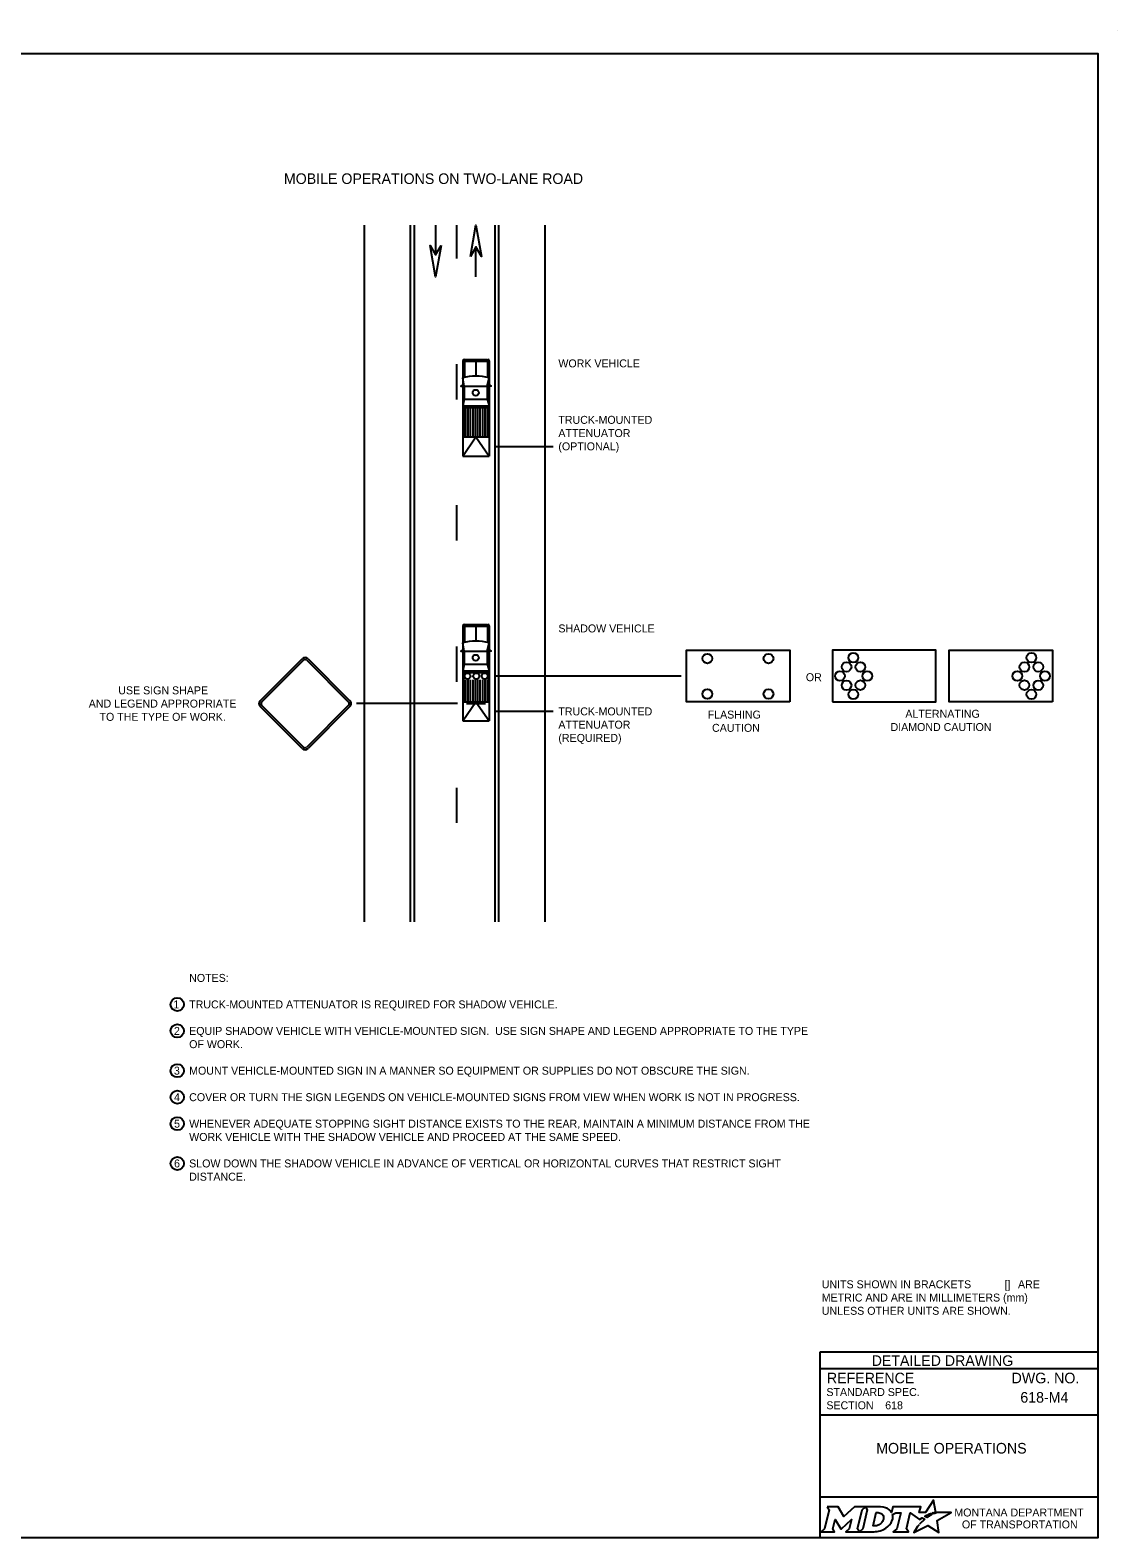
# Model space of a CAD drawing. Extents: x 49991.4 to 50021, y 49987.6 to 50011.4.
# Drawn here: x 50008.69 to 50016.9, y 49987.8 to 49999.18 of the extents above; entities that cross this region are included whole.
import ezdxf

# ---------------------------------------------------------------- set-up
doc = ezdxf.new("R2010")
doc.units = 0
for name, color, linetype in [('Default', 7, 'Continuous'), ('Level 1', 7, 'Continuous'), ('Level 2', 7, 'Continuous'), ('Level 3', 7, 'Continuous'), ('Level 5', 7, 'Continuous')]:
    doc.layers.add(name, color=color, linetype=linetype)

msp = doc.modelspace()

# ---------------------------------------------------------------- linework, layer by layer
at = {"layer": 'Default'}
for points in [[(50015.513, 49987.981), (50015.502, 49987.987), (50015.514, 49987.99), (50015.526, 49987.991), (50015.508, 49988.082), (50015.449, 49987.99), (50015.401, 49987.99), (50015.412, 49988.034), (50015.202, 49988.034), (50015.192, 49987.991), (50015.186, 49988)], [(50014.706, 49988.034), (50014.72, 49988.01), (50014.686, 49987.867), (50014.66, 49987.845), (50014.762, 49987.845), (50014.749, 49987.867), (50014.765, 49987.937), (50014.809, 49987.868), (50014.814, 49987.868), (50014.889, 49987.938), (50014.872, 49987.867), (50014.848, 49987.845), (50014.949, 49987.845), (50014.936, 49987.868), (50014.969, 49988.011)], [(50014.969, 49988.011), (50014.994, 49988.034), (50014.912, 49988.034), (50014.832, 49987.961), (50014.788, 49988.034), (50014.706, 49988.034)], [(50015.108, 49988.034), (50014.994, 49988.034), (50015.009, 49988.011), (50014.975, 49987.867), (50014.949, 49987.845), (50015.06, 49987.845)], [(50015.132, 49987.947), (50015.13, 49987.939), (50015.127, 49987.93), (50015.123, 49987.922), (50015.118, 49987.914), (50015.111, 49987.907), (50015.103, 49987.901), (50015.095, 49987.896), (50015.086, 49987.892), (50015.077, 49987.89), (50015.067, 49987.889), (50015.052, 49987.889), (50015.075, 49987.989), (50015.091, 49987.989), (50015.099, 49987.988), (50015.106, 49987.986), (50015.113, 49987.983), (50015.119, 49987.979), (50015.124, 49987.974), (50015.128, 49987.968), (50015.13, 49987.962), (50015.132, 49987.955), (50015.132, 49987.952), (50015.132, 49987.947)], [(50015.199, 49987.975), (50015.224, 49987.988), (50015.261, 49987.988), (50015.232, 49987.867), (50015.205, 49987.845), (50015.321, 49987.845), (50015.304, 49987.867), (50015.332, 49987.988), (50015.403, 49987.936), (50015.424, 49987.951), (50015.444, 49987.94)], [(50015.388, 49987.884), (50015.373, 49987.86), (50015.368, 49987.852), (50015.362, 49987.844), (50015.36, 49987.839), (50015.465, 49987.893), (50015.549, 49987.838), (50015.536, 49987.93), (50015.643, 49987.989), (50015.594, 49987.989), (50015.564, 49987.99), (50015.543, 49987.99), (50015.536, 49987.989), (50015.531, 49987.987), (50015.523, 49987.985), (50015.513, 49987.981)], [(50015.462, 49987.954), (50015.46, 49987.952), (50015.442, 49987.961), (50015.452, 49987.967), (50015.456, 49987.969), (50015.465, 49987.973), (50015.47, 49987.976), (50015.478, 49987.979), (50015.485, 49987.982), (50015.497, 49987.974), (50015.493, 49987.972), (50015.489, 49987.97), (50015.484, 49987.967), (50015.479, 49987.965), (50015.478, 49987.963), (50015.475, 49987.962), (50015.472, 49987.96), (50015.47, 49987.959), (50015.467, 49987.957), (50015.465, 49987.955), (50015.462, 49987.954)], [(50015.106, 49987.852), (50015.114, 49987.855), (50015.127, 49987.86), (50015.148, 49987.871)], [(50015.402, 49987.9), (50015.402, 49987.9)]]:
    msp.add_lwpolyline(points, dxfattribs=at)
for centre, radius, start, end in [((50015.087, 49987.973), 0.118, 300.9103, 339.1383), ((50015.131, 49987.955), 0.0709, 339.5329, 15.8582)]:
    msp.add_arc(centre, radius, start, end, dxfattribs=at)
for centre, major_axis, ratio, start_param, end_param in [((50015.106, 49987.986), (0.0834, -0.0037), 0.568097, 0.61298, 1.570796), ((50015.161, 49987.994), (0.0361, -0.0295), 0.469099, 1.225588, 1.570796), ((50015.433, 49987.93), (-0.0112, -0.0097), 0.021651, 3.157348, 6.283185), ((50015.06, 49987.993), (0, 0.148), 0.987302, 3.139398, 3.456847), ((50015.395, 49987.892), (-0.00694, -0.00806), 0.008222, 0, 3.137361), ((50015.412, 49987.911), (-0.0098, -0.0102), 0.016458, 3.141593, 6.279097)]:
    msp.add_ellipse(centre, major_axis=major_axis, ratio=ratio, start_param=start_param, end_param=end_param, dxfattribs=at)
at = {"layer": 'Level 1'}
for p, q in [((50016.9, 49999.176), (50016.9, 49999.176)), ((50011.213, 49992.446), (50011.213, 49997.704)), ((50011.561, 49992.446), (50011.561, 49997.704)), ((50011.59, 49992.446), (50011.59, 49997.704)), ((50011.75, 49997.704), (50011.75, 49997.479)), ((50011.75, 49997.704), (50011.75, 49997.479)), ((50011.91, 49997.453), (50011.91, 49997.704)), ((50012.199, 49992.446), (50012.199, 49997.704)), ((50012.228, 49992.446), (50012.228, 49997.704)), ((50012.577, 49992.446), (50012.577, 49997.704)), ((50012.055, 49997.314), (50012.055, 49997.54)), ((50012.055, 49997.314), (50012.055, 49997.54)), ((50011.968, 49996.678), (50011.96, 49996.688)), ((50011.968, 49996.691), (50012.143, 49996.691)), ((50012.143, 49996.678), (50012.151, 49996.687)), ((50011.91, 49996.389), (50011.91, 49996.656)), ((50011.955, 49996.678), (50011.955, 49995.962)), ((50011.968, 49996.678), (50012.143, 49996.678)), ((50011.968, 49996.678), (50011.968, 49996.56)), ((50012.055, 49996.678), (50012.055, 49996.573)), ((50012.143, 49996.678), (50012.143, 49996.56)), ((50012.154, 49996.68), (50012.154, 49995.962)), ((50011.966, 49996.49), (50011.955, 49996.551)), ((50011.966, 49996.49), (50012.14, 49996.49)), ((50011.966, 49996.49), (50011.966, 49996.391)), ((50012.14, 49996.49), (50012.154, 49996.551)), ((50012.14, 49996.49), (50012.14, 49996.391)), ((50011.966, 49996.39), (50011.955, 49996.34)), ((50011.966, 49996.39), (50012.14, 49996.39)), ((50012.14, 49996.39), (50012.154, 49996.34)), ((50011.955, 49996.34), (50012.154, 49996.34)), ((50011.955, 49996.329), (50012.154, 49996.329)), ((50011.961, 49996.329), (50011.961, 49996.214)), ((50011.976, 49996.329), (50011.976, 49996.107)), ((50011.994, 49996.329), (50011.994, 49996.107)), ((50012.012, 49996.329), (50012.012, 49996.107)), ((50012.031, 49996.329), (50012.031, 49996.107)), ((50012.049, 49996.329), (50012.049, 49996.107)), ((50012.067, 49996.329), (50012.067, 49996.107)), ((50012.085, 49996.329), (50012.085, 49996.107)), ((50012.104, 49996.329), (50012.104, 49996.107)), ((50012.122, 49996.329), (50012.122, 49996.107)), ((50012.14, 49996.329), (50012.14, 49996.107)), ((50012.148, 49996.329), (50012.148, 49996.214)), ((50011.962, 49996.214), (50011.955, 49996.214)), ((50011.962, 49996.161), (50011.955, 49996.161)), ((50011.961, 49996.161), (50011.961, 49996.107)), ((50011.966, 49996.209), (50011.966, 49996.165)), ((50012.143, 49996.209), (50012.143, 49996.165)), ((50012.148, 49996.214), (50012.154, 49996.214)), ((50012.148, 49996.161), (50012.154, 49996.161)), ((50012.148, 49996.161), (50012.148, 49996.107)), ((50011.955, 49996.107), (50012.154, 49996.107)), ((50011.955, 49995.962), (50012.154, 49995.962)), ((50011.91, 49995.324), (50011.91, 49995.59)), ((50011.955, 49994.679), (50011.955, 49993.963)), ((50011.968, 49994.678), (50011.96, 49994.688)), ((50011.968, 49994.691), (50012.143, 49994.691)), ((50011.968, 49994.678), (50012.143, 49994.678)), ((50011.968, 49994.678), (50011.968, 49994.561)), ((50012.055, 49994.678), (50012.055, 49994.574)), ((50012.143, 49994.678), (50012.151, 49994.687)), ((50012.143, 49994.678), (50012.143, 49994.561)), ((50012.154, 49994.681), (50012.154, 49993.963)), ((50011.91, 49994.258), (50011.91, 49994.525)), ((50011.966, 49994.49), (50011.955, 49994.552)), ((50012.14, 49994.49), (50012.154, 49994.552)), ((50010.427, 49994.116), (50010.742, 49994.432)), ((50010.437, 49994.105), (50010.753, 49994.421)), ((50010.777, 49994.421), (50011.093, 49994.105)), ((50010.788, 49994.432), (50011.103, 49994.116)), ((50011.966, 49994.49), (50012.14, 49994.49)), ((50011.966, 49994.49), (50011.966, 49994.391)), ((50012.14, 49994.49), (50012.14, 49994.391)), ((50011.966, 49994.391), (50011.955, 49994.341)), ((50011.955, 49994.341), (50012.154, 49994.341)), ((50011.955, 49994.329), (50012.154, 49994.329)), ((50011.961, 49994.329), (50011.961, 49994.214)), ((50011.966, 49994.391), (50012.14, 49994.391)), ((50012.14, 49994.391), (50012.154, 49994.341)), ((50012.148, 49994.329), (50012.148, 49994.214)), ((50011.962, 49994.214), (50011.955, 49994.214)), ((50011.966, 49994.209), (50011.966, 49994.166)), ((50011.976, 49994.274), (50011.976, 49994.107)), ((50011.994, 49994.274), (50011.994, 49994.107)), ((50012.012, 49994.274), (50012.012, 49994.107)), ((50012.031, 49994.274), (50012.031, 49994.107)), ((50012.049, 49994.274), (50012.049, 49994.107)), ((50012.067, 49994.274), (50012.067, 49994.107)), ((50012.085, 49994.274), (50012.085, 49994.107)), ((50012.104, 49994.274), (50012.104, 49994.107)), ((50012.122, 49994.274), (50012.122, 49994.107)), ((50012.14, 49994.274), (50012.14, 49994.107)), ((50012.143, 49994.209), (50012.143, 49994.166)), ((50012.148, 49994.214), (50012.154, 49994.214)), ((50010.742, 49993.755), (50010.427, 49994.071)), ((50010.753, 49993.766), (50010.437, 49994.082)), ((50010.753, 49993.766), (50010.437, 49994.082)), ((50010.437, 49994.082), (50010.753, 49993.766)), ((50011.093, 49994.082), (50010.777, 49993.766)), ((50011.103, 49994.071), (50010.788, 49993.755)), ((50011.962, 49994.161), (50011.955, 49994.161)), ((50011.955, 49994.107), (50012.154, 49994.107)), ((50011.961, 49994.161), (50011.961, 49994.107)), ((50011.983, 49994.094), (50012.126, 49994.094)), ((50012.148, 49994.161), (50012.154, 49994.161)), ((50012.148, 49994.161), (50012.148, 49994.107)), ((50011.955, 49993.963), (50012.154, 49993.963)), ((50011.91, 49993.193), (50011.91, 49993.459))]:
    msp.add_line(p, q, dxfattribs=at)
for points in [[(49999.384, 49998.999), (50016.75, 49998.999), (50016.75, 49987.799), (49999.384, 49987.799)], [(50012.013, 49997.468), (50012.055, 49997.704), (50012.097, 49997.468), (50012.055, 49997.54)], [(50011.792, 49997.551), (50011.75, 49997.314), (50011.708, 49997.551), (50011.75, 49997.479)], [(50014.424, 49994.107), (50013.644, 49994.107), (50013.644, 49994.497), (50014.424, 49994.497)], [(50014.424, 49994.107), (50013.644, 49994.107), (50013.644, 49994.497), (50014.424, 49994.497)]]:
    msp.add_lwpolyline(points, close=True, dxfattribs=at)
for points in [[(50011.963, 49996.489), (50011.95, 49996.497), (50011.94, 49996.489), (50011.963, 49996.489)], [(50012.147, 49996.489), (50012.16, 49996.497), (50012.17, 49996.489), (50012.147, 49996.489)], [(50011.955, 49995.962), (50012.055, 49996.107), (50012.154, 49995.962)], [(50011.963, 49994.489), (50011.95, 49994.497), (50011.94, 49994.489), (50011.963, 49994.489)], [(50012.147, 49994.49), (50012.16, 49994.497), (50012.17, 49994.49), (50012.147, 49994.49)], [(50014.745, 49994.107), (50015.525, 49994.107), (50015.525, 49994.497), (50014.745, 49994.497), (50014.745, 49994.107)], [(50016.407, 49994.107), (50015.627, 49994.107), (50015.627, 49994.497), (50016.407, 49994.497), (50016.407, 49994.107)], [(50011.955, 49993.963), (50012.055, 49994.107), (50012.154, 49993.963)]]:
    msp.add_lwpolyline(points, dxfattribs=at)
for centre, radius in [((50012.053, 49996.44), 0.0227), ((50012.053, 49994.44), 0.0227), ((50013.802, 49994.434), 0.0366), ((50014.263, 49994.434), 0.0366), ((50014.903, 49994.44), 0.0366), ((50016.248, 49994.44), 0.0366), ((50011.991, 49994.302), 0.0227), ((50012.057, 49994.302), 0.0227), ((50012.121, 49994.302), 0.0227), ((50014.802, 49994.302), 0.0366), ((50014.852, 49994.371), 0.0366), ((50014.957, 49994.37), 0.0366), ((50015.009, 49994.302), 0.0366), ((50016.142, 49994.302), 0.0366), ((50016.195, 49994.37), 0.0366), ((50016.299, 49994.371), 0.0366), ((50016.35, 49994.302), 0.0366), ((50013.802, 49994.167), 0.0366), ((50014.263, 49994.167), 0.0366), ((50014.852, 49994.232), 0.0366), ((50014.903, 49994.163), 0.0366), ((50014.957, 49994.233), 0.0366), ((50016.195, 49994.233), 0.0366), ((50016.248, 49994.163), 0.0366), ((50016.299, 49994.232), 0.0366)]:
    msp.add_circle(centre, radius, dxfattribs=at)
for centre, radius, start, end in [((50011.968, 49996.678), 0.0135, 92.7859, 176.3711), ((50012.143, 49996.679), 0.0118, 5.1286, 87.8426), ((50012.054, 49996.19), 0.375, 74.595, 105.405), ((50011.962, 49996.209), 0.00458, 0, 90), ((50011.962, 49996.165), 0.00458, 270, 0), ((50012.148, 49996.209), 0.00458, 90, 180), ((50012.148, 49996.165), 0.00458, 180, 270), ((50011.968, 49994.678), 0.0135, 92.7859, 176.3711), ((50012.143, 49994.68), 0.0118, 5.1286, 87.8426), ((50012.054, 49994.19), 0.375, 74.595, 105.405), ((50010.765, 49994.409), 0.0319, 45.0001, 134.9999), ((50010.765, 49994.409), 0.0168, 45.0001, 134.9999), ((50011.962, 49994.209), 0.00458, 0, 90), ((50012.148, 49994.209), 0.00458, 90, 180), ((50010.449, 49994.094), 0.0319, 134.9999, 225.0001), ((50010.449, 49994.094), 0.0168, 134.9999, 225.0001), ((50011.081, 49994.094), 0.0168, 314.9999, 45.0001), ((50011.081, 49994.094), 0.0319, 314.9999, 45.0001), ((50011.962, 49994.166), 0.00458, 270, 0), ((50012.148, 49994.166), 0.00458, 180, 270), ((50010.765, 49993.778), 0.0319, 225.0001, 314.9999), ((50010.765, 49993.778), 0.0168, 225.0001, 314.9999)]:
    msp.add_arc(centre, radius, start, end, dxfattribs=at)
at = {"layer": 'Level 2'}
for centre in [(50009.8, 49991.824), (50009.8, 49991.624), (50009.8, 49991.324), (50009.8, 49991.124), (50009.8, 49990.924), (50009.8, 49990.624)]:
    msp.add_circle(centre, 0.05, dxfattribs=at)
at = {"layer": 'Level 3'}
for p, q in [((50012.194, 49996.035), (50012.637, 49996.035)), ((50013.604, 49994.302), (50012.194, 49994.302)), ((50011.915, 49994.094), (50011.153, 49994.094)), ((50012.637, 49994.035), (50012.194, 49994.035))]:
    msp.add_line(p, q, dxfattribs=at)
at = {"layer": 'Level 5'}
for p, q in [((50016.75, 49989.199), (50014.65, 49989.199)), ((50014.65, 49989.199), (50014.65, 49987.799)), ((50016.75, 49989.074), (50014.65, 49989.074)), ((50016.386, 49988.859), (50016.386, 49988.859)), ((50016.75, 49988.724), (50014.65, 49988.724)), ((50015.144, 49988.799), (50015.144, 49988.799)), ((50015.7, 49988.475), (50015.7, 49988.475)), ((50016.75, 49988.106), (50014.65, 49988.106))]:
    msp.add_line(p, q, dxfattribs=at)

# ---------------------------------------------------------------- texts
at = {"layer": 'Default'}
for s, p in [('MONTANA DEPARTMENT', (50015.666, 49987.96)), ('OF TRANSPORTATION', (50015.723, 49987.87))]:
    msp.add_text(s, height=0.06, dxfattribs=at).set_placement(p)
at = {"layer": 'Level 2'}
for s, height, p in [('MOBILE OPERATIONS ON TWO-LANE ROAD', 0.08, (50010.605, 49998.015)), ('WORK VEHICLE', 0.06, (50012.677, 49996.631)), ('TRUCK-MOUNTED', 0.06, (50012.677, 49996.205)), ('ATTENUATOR', 0.06, (50012.677, 49996.105)), ('(OPTIONAL)', 0.06, (50012.677, 49996.005)), ('SHADOW VEHICLE', 0.06, (50012.677, 49994.631)), ('OR', 0.06, (50014.545, 49994.263)), ('USE SIGN SHAPE', 0.06, (50009.355, 49994.164)), ('AND LEGEND APPROPRIATE', 0.06, (50009.132, 49994.064)), ('TO THE TYPE OF WORK.', 0.06, (50009.213, 49993.964)), ('ATTENUATOR', 0.06, (50012.677, 49993.905)), ('TRUCK-MOUNTED', 0.06, (50012.677, 49994.005)), ('FLASHING', 0.06, (50013.804, 49993.981)), ('ALTERNATING ', 0.06, (50015.296, 49993.987)), ('(REQUIRED)', 0.06, (50012.677, 49993.805)), ('CAUTION', 0.06, (50013.837, 49993.881)), ('DIAMOND CAUTION', 0.06, (50015.184, 49993.887)), ('NOTES:', 0.06, (50009.89, 49991.994)), ('1', 0.06, (50009.771, 49991.794)), ('TRUCK-MOUNTED ATTENUATOR IS REQUIRED FOR SHADOW VEHICLE.', 0.06, (50009.89, 49991.794)), ('2', 0.06, (50009.775, 49991.594)), ('EQUIP SHADOW VEHICLE WITH VEHICLE-MOUNTED SIGN.  USE SIGN SHAPE AND LEGEND APPROPRIATE TO THE TYPE ', 0.06, (50009.89, 49991.594)), ('OF WORK.', 0.06, (50009.89, 49991.494)), ('3', 0.06, (50009.775, 49991.294)), ('MOUNT VEHICLE-MOUNTED SIGN IN A MANNER SO EQUIPMENT OR SUPPLIES DO NOT OBSCURE THE SIGN.', 0.06, (50009.89, 49991.294)), ('4', 0.06, (50009.776, 49991.094)), ('COVER OR TURN THE SIGN LEGENDS ON VEHICLE-MOUNTED SIGNS FROM VIEW WHEN WORK IS NOT IN PROGRESS.', 0.06, (50009.89, 49991.094)), ('5', 0.06, (50009.776, 49990.894)), ('WHENEVER ADEQUATE STOPPING SIGHT DISTANCE EXISTS TO THE REAR, MAINTAIN A MINIMUM DISTANCE FROM THE ', 0.06, (50009.89, 49990.894)), ('WORK VEHICLE WITH THE SHADOW VEHICLE AND PROCEED AT THE SAME SPEED.', 0.06, (50009.89, 49990.794)), ('6', 0.06, (50009.776, 49990.594)), ('SLOW DOWN THE SHADOW VEHICLE IN ADVANCE OF VERTICAL OR HORIZONTAL CURVES THAT RESTRICT SIGHT ', 0.06, (50009.89, 49990.594)), ('DISTANCE.', 0.06, (50009.89, 49990.494)), ('UNITS SHOWN IN BRACKETS ', 0.06, (50014.665, 49989.682)), ('METRIC AND ARE IN MILLIMETERS (mm) ', 0.06, (50014.665, 49989.582)), ('[]', 0.06, (50016.045, 49989.682)), (' ARE ', 0.06, (50016.124, 49989.682)), ('UNLESS OTHER UNITS ARE SHOWN.', 0.06, (50014.665, 49989.482)), ('618-M4', 0.08, (50016.164, 49988.819)), ('618', 0.06, (50015.144, 49988.769)), ('MOBILE OPERATIONS', 0.08, (50015.076, 49988.435))]:
    msp.add_text(s, height=height, dxfattribs=at).set_placement(p)
at = {"layer": 'Level 5'}
for s, height, p in [('DETAILED DRAWING', 0.0799, (50015.042, 49989.096)), ('REFERENCE', 0.08, (50014.704, 49988.965)), ('DWG. NO.', 0.08, (50016.098, 49988.965)), ('STANDARD SPEC.', 0.06, (50014.7, 49988.869)), ('SECTION', 0.06, (50014.7, 49988.769))]:
    msp.add_text(s, height=height, dxfattribs=at).set_placement(p)

doc.saveas('drawing.dxf')
